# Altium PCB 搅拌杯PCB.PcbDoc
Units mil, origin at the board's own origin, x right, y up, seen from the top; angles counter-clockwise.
Board outline 1417.32 x 1279.53 mil, 2 copper layers (Top Layer, Bottom Layer); 74 components, 45 nets, 191 pads, 39 vias.
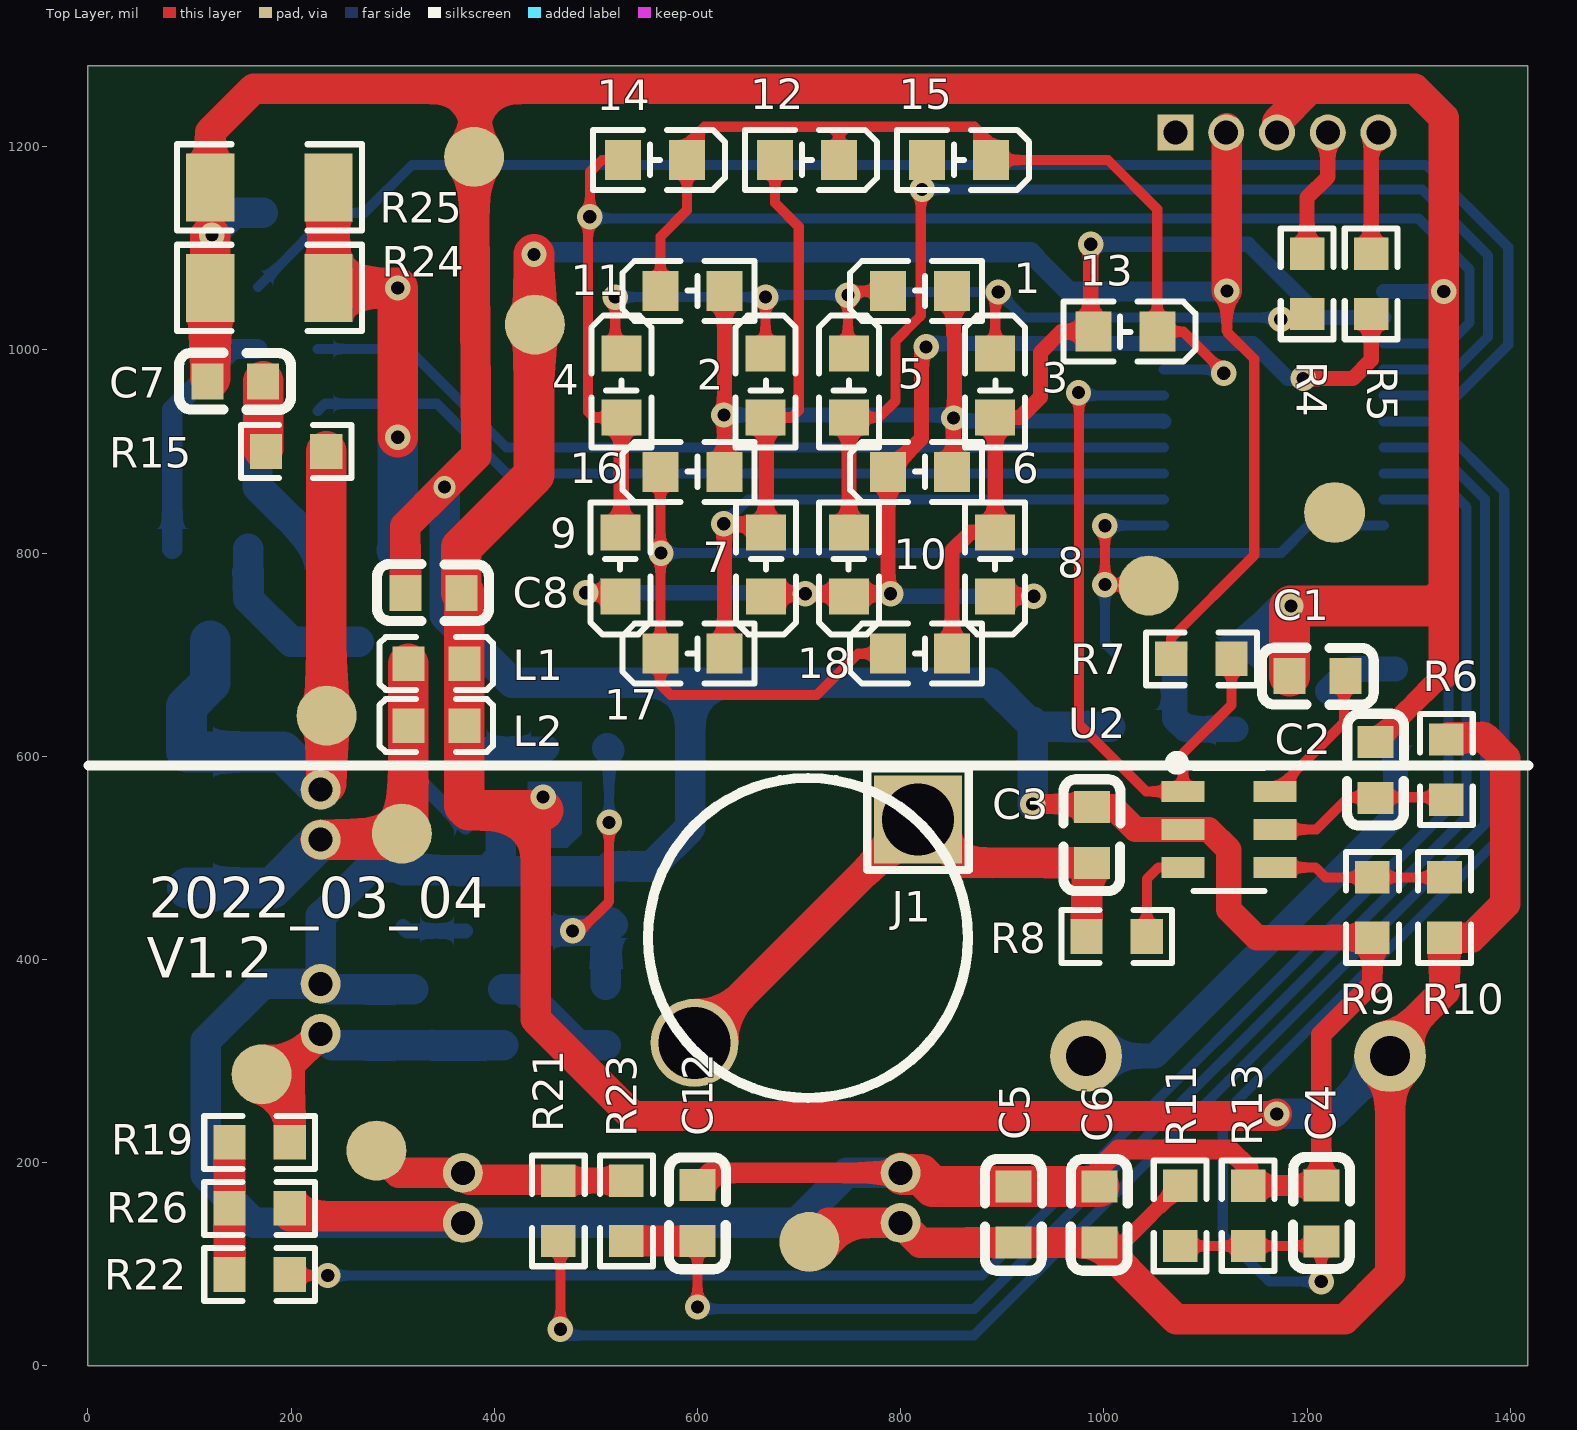
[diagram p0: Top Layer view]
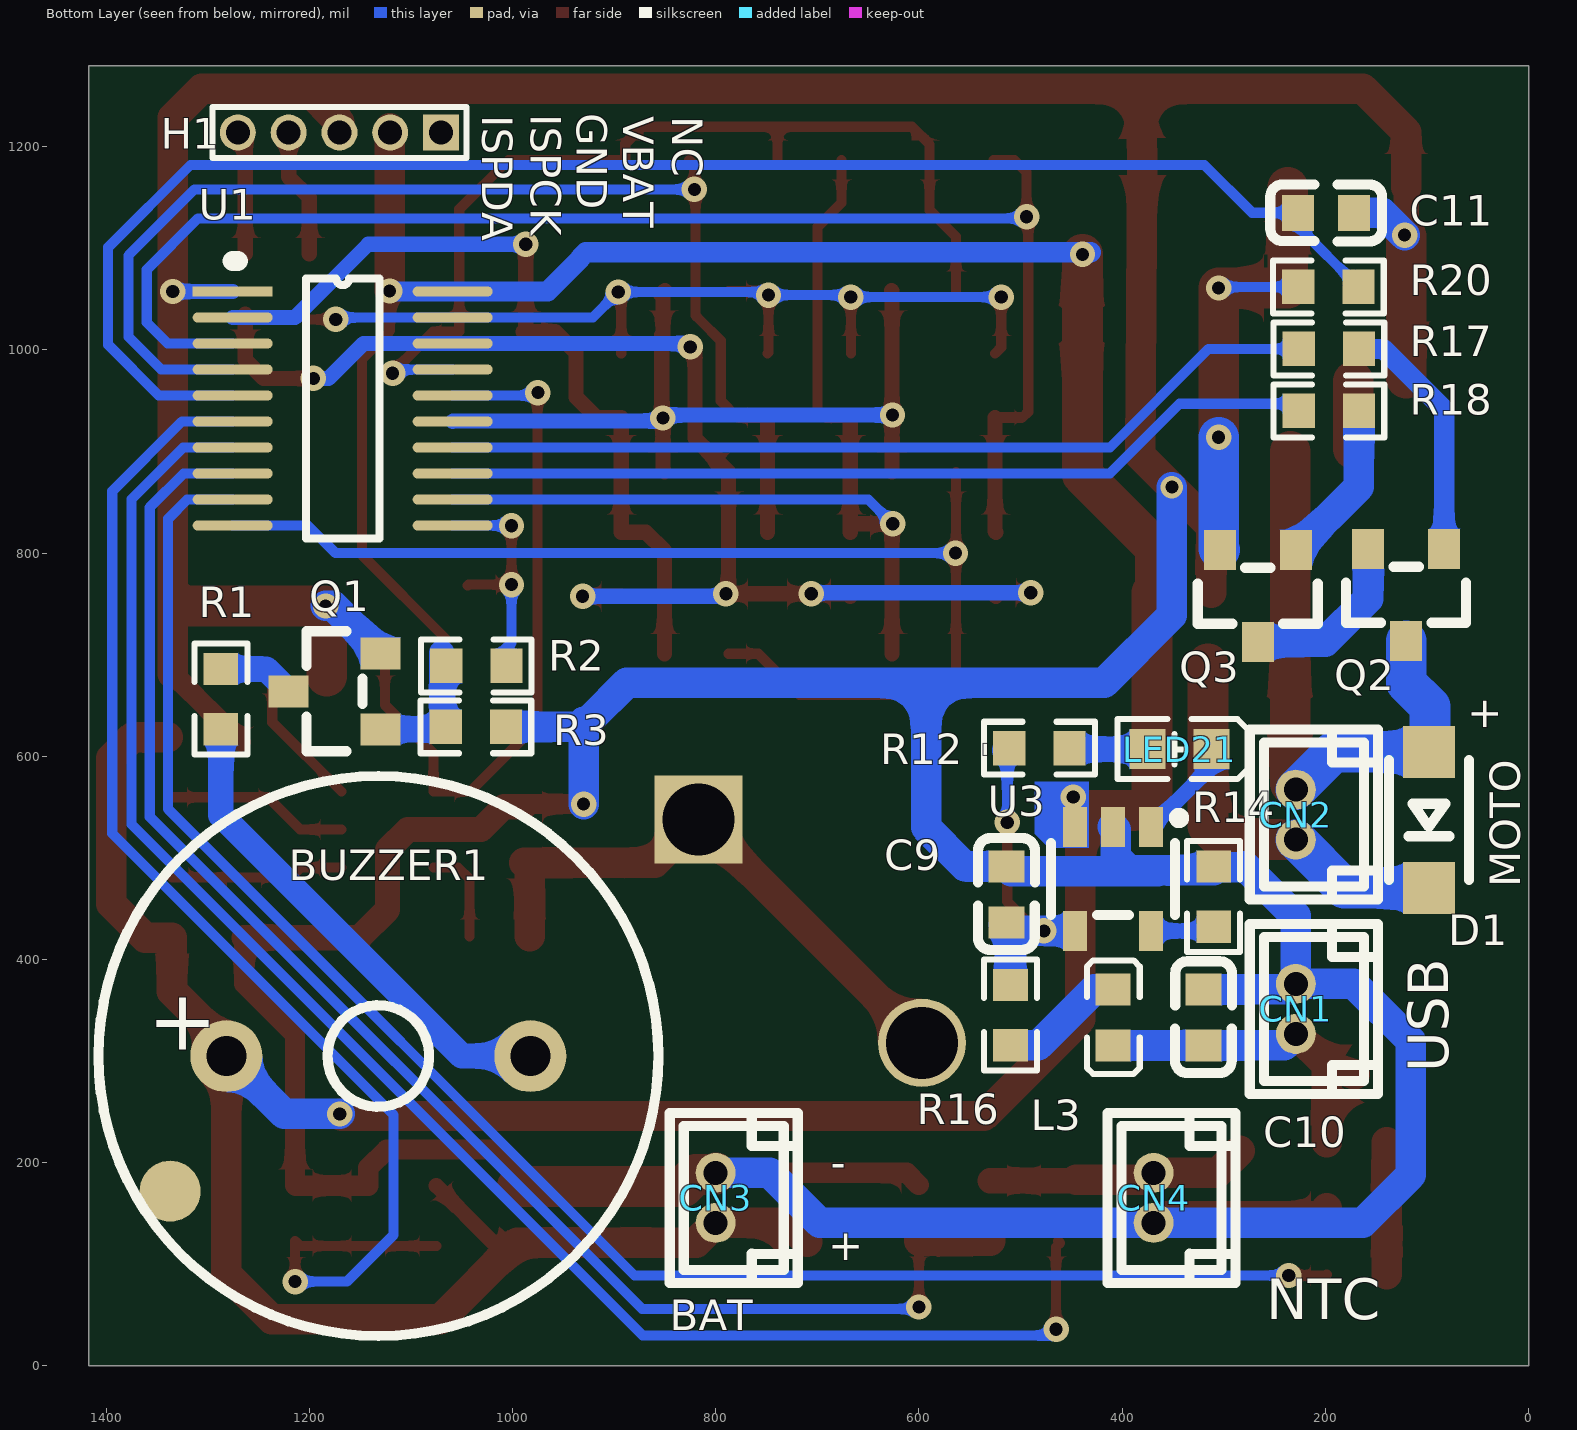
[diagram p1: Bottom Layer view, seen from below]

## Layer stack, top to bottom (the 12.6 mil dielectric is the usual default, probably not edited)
Top Solder: solder mask 0.4, Solder Resist, Dk 3.5
Top Layer: signal copper 1.4
Dielectric 1: dielectric 12.6, FR-4, Dk 4.8
Bottom Layer: signal copper 1.4
Bottom Solder: solder mask 0.4, Solder Resist, Dk 3.5

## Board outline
0,0 0,1279.53 1417.32,1279.53 1417.32,0

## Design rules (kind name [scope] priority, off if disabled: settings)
Clearance [All] p1: gap=8
ComponentClearance [All] p1 off: gap=10 collisioncheckmode=3 verticalgap=10 showdistances=FALSE
PolygonConnect [All] p1: connectstyle=Relief reliefconductorwidth=10 reliefentries=4 polygonreliefangle="90 Angle" airgapwidth=10
RoutingVias [All] p1: holewidth=28 width=50 viastyle="Through Hole" minholewidth=10 minwidth=10 maxholewidth=28 maxwidth=50
SolderMaskExpansion [All] p1: expansion=4
Width [All] p1: maxlimit=50 minlimit=8 preferedwidth=10
29 further rules are at their usual default settings.

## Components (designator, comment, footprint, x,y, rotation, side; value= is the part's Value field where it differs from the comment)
1 "LED-0603_W" LED0603-FD_WHITE 819,1058 r180 top (schematic designator LED1)
2 "LED-0603_W" LED0603-FD_WHITE 667,965 r90 top (schematic designator LED2)
3 "LED-0603_W" LED0603-FD_WHITE 893,965 r90 top (schematic designator LED3)
4 "LED-0603_W" LED0603-FD_WHITE 525,965 r90 top (schematic designator LED4)
5 "LED-0603_W" LED0603-FD_WHITE 749,965 r90 top (schematic designator LED5)
6 "LED-0603_W" LED0603-FD_WHITE 819,880 r180 top (schematic designator LED6)
7 "LED-0603_W" LED0603-FD_WHITE 667.53,789 r270 top (schematic designator LED7)
8 "LED-0603_W" LED0603-FD_WHITE 893,789 r270 top (schematic designator LED8)
9 "LED-0603_W" LED0603-FD_WHITE 524,789 r270 top (schematic designator LED9)
10 "LED-0603_W" LED0603-FD_WHITE 749,789 r270 top (schematic designator LED10)
11 "LED-0603_W" LED0603-FD_WHITE 595,1058 r180 top (schematic designator LED11)
12 "LED-0603_W" LED0603-FD_WHITE 707.75,1187 r0 top (schematic designator LED12)
13 "LED-0603_W" LED0603-FD_WHITE 1021,1018 r0 top (schematic designator LED13)
14 "LED-0603_W" LED0603-FD_WHITE 558,1187 r0 top (schematic designator LED14)
15 "LED-0603_W" LED0603-FD_WHITE 857.51,1187 r0 top (schematic designator LED15)
16 "LED-0603_W" LED0603-FD_WHITE 595,880 r180 top (schematic designator LED16)
17 "LED-0603_W" LED0603-FD_WHITE 595,701 r180 top (schematic designator LED17)
18 "LED-0603_W" LED0603-FD_WHITE 819,701 r180 top (schematic designator LED18)
BUZZER1 "FMQ-BUZZER2" BUZ-TH_BD12.0-P7.60-D0.6-FD 1132,305 r180 bottom
C1 "4.7nF" C0603 1210.24,678.92 r180 top
C2 "0.1u" C0603 1267.24,586.54 r270 top
C3 "nc" C0603 988.22,522.69 r90 top
C4 "0.1u" C0603 1214,150.23 r270 top
C5 "1uF" C0603 911,149 r90 top
C6 "0.1u" C0603 995.5,149 r90 top
C7 "0.1u" C0603 145,969 r0 top
C8 "10uF" C0603 340,761 r0 top
C9 "4.7uF" C0603 514,464.19 r270 bottom
C10 "10uF" C0603 320,343 r270 bottom
C11 "0.1u" C0603 199.44,1135 r0 bottom
C12 "0.1u" C0603 600,150.44 r90 top
CN1 "0530470210" CONN-TH_0530470210 229,351.39 r90 bottom
CN2 "0530470210" CONN-TH_0530470210 229,542.61 r90 bottom
CN3 "0530470210" CONN-TH_0530470210 800,165.39 r90 bottom
CN4 "0530470210" CONN-TH_0530470210 369,165.39 r90 bottom
D1 "1N4148W" SOD-123FL_L2.6-W1.6-LS3.4-RD 98,537.33 r270 bottom
H1 "HDR-F-2.54_1x5" 1.27mm_5PIN 1070.34,1214 r0 bottom
J1 "HDR-M-2.54_1x1" HDR-M-2.54_1X1 817,538 r0 top
L1 "22uH" L0603 343,691 r0 top
L2 "22uH" L0603 343,629.97 r0 top
L3 "BEAD" L0603 409,343 r270 bottom
LED21 "LED-0603_W" LED0603-FD_WHITE 343.5,607 r180 bottom
Q1 "2N7002" SOT-23_L2.9-W1.3-P0.95-LS2.4-BR 1175.07,664.01 r180 bottom
Q2 "2N7002" SOT-23_L2.9-W1.3-P0.95-LS2.4-BR 120.43,759 r90 bottom
Q3 "2N7002" SOT-23_L2.9-W1.3-P0.95-LS2.4-BR 266.43,758 r90 bottom
R1 "100R" R0603 1287,656.35 r90 bottom
R2 "1K" R0603 1035.66,689 r180 bottom
R3 "100K" R0603 1036.07,629.01 r180 bottom
R4 "100R" R0603 1200,1065 r270 top
R5 "100R" R0603 1263,1065 r270 top
R6 "0R" R0603 1337,587 r90 top
R7 "10K" R0603 1096,696 r180 top
R8 "1K" R0603 1012.58,422.69 r180 top
R9 "NC" R0603 1264.24,451.21 r90 top
R10 "NC" R0603 1335.24,451.21 r90 top
R11 "3M" R0603 1075,147.69 r90 top
R12 "1k" R0603 481.35,608 r180 bottom
R13 "1M" R0603 1142,147.79 r270 top
R14 "1k" R0603 310,462 r90 bottom
R15 "1k" R0603 205,900 r0 top
R16 "NC" R0603 509.84,345.35 r270 bottom
R17 "100R" R0603 196.55,1001 r180 bottom
R18 "100R" R0603 196.55,940 r180 bottom
R19 "1k" R0603 169,220 r0 top
R20 "1k" R0603 197,1062 r180 bottom
R21 "330K" R0603 463,152.64 r90 top
R22 "1k" R0603 169,90 r0 top
R23 "1k" R0603 530,152.64 r270 top
R24 "1R" R1206 178.65,1061 r0 top
R25 "1R" R1206 178.65,1160 r0 top
R26 "33K" R0603 169,155 r0 top
U1 "ES7P0693FHTF" TSOP20 1275.4,1057.54 r180 bottom
U2 "AS01C(AI01)" SOT-23-6_L2.9-W1.6-P0.95-LS2.8-BL 1123.11,528 r270 top
U3 "HE4054B" SOT-23-5_L3.0-W1.7-P0.95-LS2.8-BR 409,479.34 r90 bottom

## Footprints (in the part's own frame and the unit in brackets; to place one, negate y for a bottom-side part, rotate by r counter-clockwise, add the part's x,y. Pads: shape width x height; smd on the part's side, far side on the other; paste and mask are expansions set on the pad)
1.27mm_5PIN [mm]
  rect 0.9x0.9 hole 0.6: 1(0,0)
  round 0.9 hole 0.6: 2(1.27,0) 3(2.54,0) 4(3.81,0) 5(5.08,0)
  silkscreen extent -0.64,-0.64 5.71,0.64
BUZ-TH_BD12.0-P7.60-D0.6-FD [mm]
  round 1.8 hole 1: 1(-3.8,0) 2(3.8,0)
  silkscreen extent -7,-7 7,7
C0603 [mm]
  rect 0.8x0.9 smd: 1(-0.7,0) 2(0.7,0)
  silkscreen extent -1.41,-0.71 1.39,0.72
CONN-TH_0530470210 [mm]
  round 1 hole 0.6: 1(-0.625,0) 2(0.625,0)
  silkscreen extent -2.13,-2.05 2.13,1.15
HDR-M-2.54_1X1 [mm]
  rect 2.2x2.2 hole 1.8: 1(0,0)
  silkscreen extent -1.27,-1.27 1.27,1.27
L0603 [mm]
  rect 0.8x0.864 smd: 1(-0.7,0) 2(0.7,0)
  silkscreen extent -1.42,-0.65 1.41,0.67
LED0603-FD_WHITE [mm]
  rect 0.9x1 smd: 1(-0.8,0) 2(0.8,0)
  silkscreen extent -1.55,-0.75 1.75,0.75
R0603 [mil]
  rect 31.75x34.02 smd: 1(-29.65,0) 2(29.65,0)
  silkscreen extent -55,-26 55,26
R1206 [mil]
  rect 47.54x66.97 smd: 1(-58.22,0) 2(58.22,0)
  silkscreen extent -91,-42 91,42
SOD-123FL_L2.6-W1.6-LS3.4-RD [mm]
  rect 1.3x1.3 smd: 1(1.7,0) 2(-1.7,0)
  silkscreen extent -1.5,-1 1.5,1
SOT-23-5_L3.0-W1.7-P0.95-LS2.8-BR [mm]
  rect 1x0.6 smd: 1(1.3,-0.95) 2(1.3,0) 3(1.3,0.95) 4(-1.3,0.95) 5(-1.3,-0.95)
  silkscreen extent -0.9,-1.78 1.65,1.55
SOT-23-6_L2.9-W1.6-P0.95-LS2.8-BL [mm]
  rect 0.532x1.072 smd: 1(-0.95,-1.149) 2(0,-1.149) 3(0.95,-1.149) 4(0.95,1.149) 5(0,1.149) 6(-0.95,1.149)
  silkscreen extent -1.82,-1.45 1.54,0.89
SOT-23_L2.9-W1.3-P0.95-LS2.4-BR [mm]
  rect 1x0.8 smd: 1(1.15,-0.95) 2(1.15,0.95) 3(-1.15,0)
  silkscreen extent -0.7,-1.5 0.7,1.5
TSOP20 [mm]
  rect 2x0.25 smd: 1(0,0)
  oval 2x0.25 smd: 2(0,-0.65) 3(0,-1.3) 4(0,-1.95) 5(0,-2.6) 6(0,-3.25) 7(0,-3.9) 8(0,-4.55) 9(0,-5.2) 10(0,-5.85) 11(5.5,-5.85) 12(5.5,-5.2) 13(5.5,-4.55) 14(5.5,-3.9) 15(5.5,-3.25) 16(5.5,-2.6) 17(5.5,-1.95) 18(5.5,-1.3) 19(5.5,-0.65) 20(5.5,0)
  silkscreen extent 0,-6.18 3.66,0.76

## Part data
L3: library part 22uH
R3: library part 1K
R6 R7: library part NC
R11: library part 430k
R13: library part 430K
R21: library part 33K

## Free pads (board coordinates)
  round 86.61 hole 70.87: 0(597,318)
  round 59.06 smd: 2(171,287) 2(235,640) 2(284,212) 2(309,524) 2(380,1190) 2(440,1025) 2(710,122) 2(1044,768)
  round 60 smd: 3(1227,840)
  round 100 on Top Solder: 3(1227,840)
  round 60 smd far side: 3(1337,172)
  round 100 on Bottom Solder: 3(1337,172)

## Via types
v1: diameter 25, hole 13, Top Layer to Bottom Layer, tented both sides, 38 vias
v2: diameter 22, hole 13, Top Layer to Bottom Layer, 1 vias

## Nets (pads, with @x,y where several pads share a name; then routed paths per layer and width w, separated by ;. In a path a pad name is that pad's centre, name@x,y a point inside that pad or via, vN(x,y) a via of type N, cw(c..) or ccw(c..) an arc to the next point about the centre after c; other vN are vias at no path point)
BUZZER: pad.2@1044,768 R2.2 U1.11 | length 230.3
  Top Layer w10: v1(1001,827) v1(1001,769) 1043,769 pad.2@1044,768
  Bottom Layer w10: v1(1001,769) 1001,711.42 R2.2@1010.41,702.01 ; v1(1001,827) 1001.22,827.22 U1.11
GND: C1.2 C2.1 C3.2 C4.1 C5.2 C6.2 C7.1 C8.1 C9.1 C10.1 C11.1 C12.2 CN1.2 CN3.2 CN4.1 H1.3 pad.2@380,1190 Q1.2 R3.2 R9.1 R13.1 R14.2 R24.1 R25.1 R26.2 U1.1 U2.2 U3.2 | length 7348.2
  Top Layer w20: C12.2 612,190 CN3.2 ; v1(930,553) 985.46,553 C3.2 ; C6.2 995.5,194.5 1014,213 1124,213 1142,195 R13.1 1213.66,177.44 C4.1 1214,326 1264.24,376.24 R9.1 ; C2.1 1334.46,681.32
  Top Layer w25: C7.1 C7.1@120.43,971.99 ; v1@120.43,1113 R25.1 ; C3.2 1008.76,550.24 1031,528 U2.2 1103,528 1123,508 1123,449 1150.44,421.56 R9.1
  Top Layer w30: R25.1 120.43,1214.43 163,1257 382,1257 ; R26.2 198.65,147.32 357.94,147.32 364.48,140.78 CN4.1 ; C8.1 312.44,826.44 v2(351,865) 382,896 380,1190 382,1257 ; H1.3 1170.34,1224.34 1203,1257 ; 1329,752 1334.46,752 ; 1334.46,681.32 1334.46,752 ; 382,1257 1203,1257 ; 1203,1257 1306,1257 1334.46,1228.54 v1(1334.46,1057.54) 1334.46,752
  Top Layer w40: C7.1@120.43,971.99 R24.1 v1@120.43,1112 ; CN3.2 801.54,188.46 819.75,188.46 831.66,176.56 C6.2 ; C1.2 1182.68,746.68 v1(1184,748) 1325,748 1329,752
  Bottom Layer w15: U1.1 v1(1334.46,1057.54)
  Bottom Layer w30: v1(122,1113) 144,1135 C11.1 ; R14.2 R14.2@310,491 ; C10.1 234.44,370.56 CN1.2 ; v2(351,865) 351,739 417.79,672.21 593,672.21 ; 364.83,487 509.25,487 C9.1 554.75,491.75 593,530 593,672.21 ; U3.2 406.41,527.93 406.41,501.3 392.94,487.83 310,487.83 R14.2@310,491 ; CN3.2 747,190 697.78,140.78 CN4.1 163.22,140.78 116,188 116,320 172,376 CN1.2 ; 922.99,637.01 887.79,672.21 593,672.21 ; v1(930,553) 930,634 934.99,629.01 R3.2 ; Q1.2 1176.38,748 v1(1184,748) ; CN1.2 229,443 230,443 278.65,491.65 278.65,491 R14.2@310,491
IO_OUT: R21.1 U1.7 | length 1651
  Top Layer w10: R21.1 461,120.98 465,116.98 v1(465,36)
  Bottom Layer w10: v1(465,36) 471,30 871.91,30 1375,533.09 1375,853 1324,904 U1.7
ISPCK: H1.4 R4.1 | length 127.8
  Top Layer w15: R4.1 1200,1150 1220.34,1170.34 H1.4
ISPDA: H1.5 R5.1 | length 122.4
  Top Layer w15: R5.1 1263,1206.66 H1.5
LED_IO_0: 1.2 2.2 3.2 4.2 5.2 R4.2 U1.19 | length 980.3
  Top Layer w10: v1(519,1052) 519,1002.49 4.2 ; 2.2 v1(667,1052) ; 5.2 748,997.49 v1(748,1054) 752,1058 1.2 ; 3.2 893,1054 v1(896,1057) ; v1(1174,1030) 1202.98,1030 R4.2@1204.93,1031.95
  Bottom Layer w10: v1(519,1052) v1(667,1052) 669,1054 v1(748,1054) 745,1057 v1(896,1057) 921.05,1031.95 U1.19 1172.05,1031.95 v1(1174,1030)
LED_IO_1: 6.2 7.2 8.2 9.2 10.2 R5.2 U1.18 | length 1329.7
  Top Layer w15: v1(490,761) 525.49,761 526.49,760 9.2 ; 7.2 670.02,760 v1(706,760) v1@787.51,760 ; 6.2 v1@787.51,760 ; 6.2@789,881.49 820.5,912.99 820.5,999.5 822,998 826,1002 v1(825,1003) ; v1(790,760) v1@787.51,760 ; 8.2 v1(931,757.51) ; v1(1196,972) 1245,972 1263,990 R5.2
  Bottom Layer w15: v1(490,761) 705,761 v1(706,760) ; v1(790,760) 792.49,757.51 v1(931,757.51) ; v1@823.36,1003.08 824.28,1004 825,1003.28 v1(825,1003) 828.36,1006.36 U1.18 1146.64,1006.36 1181,972 v1(1196,972)
LED_IO_2: 11.2 12.2 13.2 14.2 15.2 U1.17 | length 963.6
  Top Layer w10: 11.2 563.51,1111.51 589.49,1137.49 14.2 589.49,1202.18 607,1219.69 739.25,1219.69 ; 12.2 739.25,1219.69 ; v1(1118,977) 1118,978 1078,1018 13.2 1052.49,1138.51 1004,1187 15.2 889,1203 872.31,1219.69 739.25,1219.69
  Bottom Layer w10: U1.17 v1@1118,980.77
LED_IO_3: 16.2 17.2 18.2 U1.10 | length 1177.1
  Top Layer w10: 16.2 17.2 563.51,670.49 573.56,660.44 717.44,660.44 758,701 18.2
  Bottom Layer w10: v1(564,800) 1174,800 1201.22,827.22 U1.10
LED_IO_4: 1.1 6.1 11.1 16.1 U1.15 | length 808.2
  Top Layer w15: 16.1 11.1 11.1@627,1058.5 ; 1.1@850,1058.5 1.1 854,1054.5 852,1052.5 852,1015.6 853,1014.6 853,934 v1(852,933) ; 6.1 852,881.5 v1(852,933) ; v1@852,935 v1(852,933)
  Bottom Layer w15: v1(626,936) v1@852,936 ; v1(852,933) v1@852,936 ; U1.15 1058.45,930 851,930 849,932 849,933 v1@852,936
LED_IO_5: 2.1 7.1 12.1 17.1 U1.12 | length 1009.1
  Top Layer w10: 2.1 692.5,933.5 699.68,940.68 699.68,1121.32 676.26,1144.74 12.1
  Top Layer w15: v1(625.82,828.82) v1@626.5,828.82 ; 17.1 v1@626.5,828.82 ; 7.1@659.21,828.82 v1@626.5,828.82 ; 2.1 667.53,932.97 7.1
  Bottom Layer w10: v1(625.82,828.82) 649.82,852.82 U1.12
LED_IO_6: 3.1 8.1 13.1 18.1 U1.2 | length 826
  Top Layer w15: 18.1 850.5,802.5 868.5,820.5 8.1 3.1 917.5,933.5 937.5,953.5 937.5,997.5 958,1018 13.1@987,1018 ; v1(987,1104) 13.1@987,1018 ; 13.1 13.1@987,1018
  Bottom Layer w15: v1(987,1104) 1142,1104 1214.05,1031.95 U1.2
LED_IO_7: 4.1 9.1 14.1 U1.3 | length 1461.8
  Top Layer w10: 4.1 498,933.5 492.31,939.19 492.31,1129.31 v1(494,1131) 494,1175 506,1187 14.1
  Top Layer w15: 9.1 525,821.49 4.1
  Bottom Layer w10: v1@490,1130 491,1131 v1(494,1131) ; v1@493.31,1133 494,1132.31 v1(494,1131) ; U1.3 1339.36,1006.36 1359.96,1026.96 1359.96,1079.04 1309.5,1129.5 495.5,1129.5 v1(494,1131)
LED_IO_8: 5.1 10.1 15.1 U1.4 | length 1195.6
  Top Layer w10: 5.1 778.5,933.5 795,950 795,1009.06 815.44,1029.5 815.5,1029.5 819.78,1033.78 819.78,1156.78 v1(821,1158) 821,1181.99 15.1
  Top Layer w15: 10.1 5.1
  Bottom Layer w10: v1(821,1158) 1313,1158 1377.96,1093.04 1377.96,1012.96 1345.77,980.77 U1.4
MOTO_CONTROL_A: R17.1 U1.14 | length 872.8
  Bottom Layer w10: R17.1 315,1001 412,904 U1.14
MOTO_CONTROL_B: R18.1 U1.13 | length 864
  Bottom Layer w10: R18.1 233.21,947 343.54,947 412.13,878.41 U1.13
MOTO_CURRERN: C11.2 R20.2 U1.5 | length 1561
  Bottom Layer w10: R20.2 227,1121.66 C11.2 272,1135 319,1182 1317,1182 1398,1101 1398,1005 1348.18,955.18 U1.5
NetBUZZER1_2: BUZZER1.2 R1.1 | length 487.5
  Bottom Layer w25: BUZZER1.2 1050,305 1287,542 R1.1
NetC1_1: C1.1 U2.6 | length 143
  Top Layer w10: U2.6 1236.52,633.58 1236.52,678.92 C1.1
NetC2_2: C2.2 R6.1 U2.5 | length 184
  Top Layer w10: U2.5 1209,528 1240.69,559.69 R6.1@1339.24,559.69
NetC3_1: C3.1 J1.1 pad.0 R8.2 | length 574.7
  Top Layer w30: pad.0 J1.1 859.87,495.13 C3.1 982.93,489.84 R8.2
NetC7_2: C7.2 R15.1 | length 70.2
  Top Layer w30: R15.1@172.56,902.79 R15.1
  Top Layer w40: R15.1@172.56,902.79 C7.2
NetC9_2: C9.2 R12.1 R16.1 U3.4 | length 328.8
  Top Layer w10: v1(477,428.16) 484.16,428.16 513,457 v1(513,535)
  Bottom Layer w10: v1(513,535) R12.1@513,606
  Bottom Layer w30: U3.4@455,428.16 v1(477,428.16) 505.52,428.16 C9.2@509.84,432.48 ; R16.1 C9.2@509.84,432.48 ; R12.1 R12.1@513,606 ; C9.2@509.84,432.48 C9.2@511.36,434 ; C9.2@511.36,434 C9.2 516.64,434 C9.2@511.36,434
NetCN2_1: CN2.1 D1.1 L1.1 L2.1 pad.2@309,524 | length 402.3
  Top Layer w40: CN2.1 302,518 315.44,531.44 L2.1 L1.1
  Bottom Layer w40: D1.1 181.4,470.4 CN2.1
NetCN2_2: CN2.2 D1.2 pad.2@235,640 Q2.3 R15.2 | length 601.1
  Top Layer w30: CN2.2 CN2.2@234.65,572.88
  Top Layer w40: CN2.2@234.65,572.88 R15.2
  Bottom Layer w40: Q2.3 120.43,672.43 97,649 97,605.26 D1.2 191.96,604.26 CN2.2
NetCN4_2: CN4.2 pad.2@284,212 R21.2 R23.1 | length 258.3
  Top Layer w25: 445,183.46 446.17,182.29 R21.2 R23.1
  Top Layer w30: pad.2@284,212 306,190 CN4.2 375.54,183.46 445,183.46
NetL3_1: L3.1 R16.2 | length 123.6
  Bottom Layer w30: L3.1 427.44,370.56 482.31,315.69 R16.2
NetLED21_1: LED21.1 R12.2 | length 77.1
  Bottom Layer w25: LED21.1 450.69,607 R12.2
NetLED21_2: LED21.2 U3.1 | length 101.2
  Bottom Layer w15: LED21.2 312.01,590.11 U3.1
NetQ1_1: Q1.1 R2.1 R3.1 | length 129.4
  Bottom Layer w25: R2.1@1069.72,702.01 1069.72,637.01 1080.13,626.6 Q1.1
NetQ1_3: Q1.3 R1.2 | length 75.8
  Bottom Layer w25: Q1.3 1242.34,686 R1.2
NetQ2_1: Q2.1 R17.2 | length 245.5
  Bottom Layer w20: Q2.1 83.03,941.03 143,1001 R17.2
NetQ2_2: Q2.2 Q3.3 | length 175.3
  Bottom Layer w30: Q2.2 157.84,755.16 200.28,712.72 Q3.3
NetQ3_1: Q3.1 R18.2 | length 162.5
  Bottom Layer w30: R18.2 166.9,865.4 Q3.1
NetQ3_2: Q3.2 R20.1 R24.2 R25.2 | length 504.1
  Top Layer w40: R25.2 R24.2 v1(305,1061) v1(305,914)
  Bottom Layer w10: R20.1 304,1062 v1(305,1061)
  Bottom Layer w40: Q3.2 305,804.44 v1(305,914)
NetR8_1: R8.1 U2.3 | length 96.9
  Top Layer w10: R8.1 1042.24,479.24 1053.6,490.6 U2.3
NetR9_2: R9.2 R10.2 U2.4 | length 170.9
  Top Layer w10: U2.4 1208.4,490.6 1218.13,480.87 R9.2 R10.2
NetR14_1: R14.1 U3.5 | length 63.3
  Bottom Layer w15: R14.1 314.19,428.15 U3.5
NetR19_1: R19.1 R22.1 R26.1 | length 130
  Top Layer w30: R22.1 R26.1 R19.1
NTC_IN: C12.1 R23.2 U1.8 | length 1501.8
  Top Layer w10: C12.1@599.91,122.98 C12.1 v1(600,58)
  Top Layer w30: R23.2 C12.1@599.91,122.98
  Bottom Layer w10: v1(600,58) 600,64 608,56 872.46,56 1357,540.54 1357,845 1323.59,878.41 U1.8
TOUCH_IN: R7.1 U1.16 U2.1 | length 697
  Top Layer w10: v1(975,958) 975,960 975.5,960.5 975.5,631.5 1041.6,565.4 U2.1 1077.87,602.87 1125.66,650.65 R7.1
  Bottom Layer w10: v1(975,958) 978,955 1058.68,955 U1.16
USB_CHECK: R22.2 U1.9 | length 1688.3
  Top Layer w10: R22.2 199.65,89 v1(236,89)
  Bottom Layer w10: v1(236,89) 880,89 1339,548 1339,834 1320.19,852.81 U1.9
USB_IN: C10.2 CN1.1 L3.2 pad.2@171,287 R19.2 | length 333.3
  Top Layer w30: pad.2@171,287 pad.2@198.65,296.43 ; R19.2 pad.2@198.65,296.43 ; CN1.1 pad.2@198.65,296.43
  Bottom Layer w30: CN1.1 240.34,315.44 C10.2 L3.2
VBAT: BUZZER1.1 C5.1 C6.1 C8.2 CN3.1 H1.2 L1.2 L2.2 pad.2@440,1025 pad.2@710,122 R6.2 R7.2 R10.1 R11.2 U1.20 U3.3 | length 4455.3
  Top Layer w10: R7.2 1066,696.35 1066,716 1148,798 1148,991 1121,1018 v1(1121,1058)
  Top Layer w15: C6.1 1019.1,121.45 R11.2
  Top Layer w30: 441,546.86 441,341 536,246 1168,246 v1(1170,248) ; pad.2@710,122 728.78,140.78 CN3.1 819.33,121.45 C6.1 1070.95,46 1237,46 1281.61,90.61 BUZZER1.1 1281.61,315.37 1335.24,369 R10.1 1361.56,421.56 1395,455 1395,598 1374,619 R6.2@1339.24,619 ; v1(1121,1058) H1.2@1121,1218
  Top Layer w40: v1(439,1094) 439,877 367.56,805.56 C8.2 370.56,761 L1.2 L2.2 370.56,551.3 375,546.86 441,546.86 448,546.86
  Bottom Layer w20: v1@431,1096 928,1096 933,1091 933,1090 965.46,1057.54 U1.20 1120.54,1057.54 v1(1121,1058) ; U3.3 446.4,565.4 449.8,562 448,560.2 v1(448,560)
  Bottom Layer w30: v1(1170,248) 1224.61,248 BUZZER1.1
VBAT_IN: C4.2 R11.1 R13.2 U1.6 | length 1290.4
  Top Layer w10: R11.1 1141.9,118.04 R13.2 1209.45,118.13 C4.2 v1(1214,83)
  Bottom Layer w10: v1(1214,83) 1163,83 1117,129 1117,247 1394,524 1394,861 1325.41,929.59 U1.6
pads on no net: H1.1

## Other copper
Bottom Layer:
  region net VBAT: 486,575 486,524 472,510 433,510 433,575

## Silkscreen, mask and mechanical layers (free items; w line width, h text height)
Top Overlay:
  circle w10: c708.66,421.29 r157.48
  lines w10: 0.57,591.09 1417.89,591.09
  text "2022_03_04" at 60,441 h40
  text "V1.2" at 58,382 h40
Bottom Overlay:
  text "GND" at 937,1233 h30 r90
  text "ISPCK" at 982,1232 h30 r90
  text "ISPDA" at 1030,1231 h30 r90
  text "NC" at 843,1230 h30 r90
  text "VBAT" at 891,1230 h30 r90
  text "+" at 30,624 h30 r270
  text "-" at 523,599 h30 r270
  text "MOTO" at 8,471 h30 r270
  text "USB" at 79,289 h40 r270
  text "-" at 687,185 h30
  text "+" at 689,104 h30
  text "NTC" at 258,46 h40
  text "BAT" at 845,35 h30
Mechanical 1:
  the board outline again, w10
